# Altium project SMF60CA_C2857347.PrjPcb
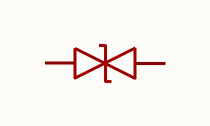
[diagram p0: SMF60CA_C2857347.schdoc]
1 sheet, 1 parts. Net scope: global (net labels, ports and power ports of the same name join across sheets).

## Sheet SMF60CA_C2857347.schdoc
size 127 x 101 mm

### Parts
D?  smf60ca_c2857347  [SOD-123FL_L2.8-W1.8-LS3.7-BI]  (value not drawn)

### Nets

Not connected (* = marked no-connect by the designer): D? 1 2

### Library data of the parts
D? = smf60ca_c2857347: 极性:双向;反向截止电压(Vrwm):60V;钳位电压:96.8V;峰值脉冲电流(Ipp):2.1A;峰值脉冲功率(Ppp):200W@10/1000us;击穿电压(VBR):66.7V;; Manufacturer: JSMSEMI(杰盛微); AddInBom: yes; ModelId: d105299b3871451c86f679efef28ff8f; ModelTransform: 145.669,70.866,0,0,0,0,0,0,0; Polarity: 双向; Reverse Stand-Off Voltage (Vrwm): 60V; Clamping Voltage: 96.8V; Peak Pulse Current (Ipp): 2.1A; Voltage - Breakdown: 66.7V; Reverse Leakage Current (Ir): 1uA; Number of Channels: 单路; Type: TVS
